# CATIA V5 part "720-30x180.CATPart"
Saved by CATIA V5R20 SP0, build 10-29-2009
Part number: 720-30x180
Definition: NONE
Nomenclature: 720-30x180
Source: Unknown
Description: 720-30x180
Bounding box of the stored display mesh (mm): x 0 to 180, y -15 to 15, z -15 to 15
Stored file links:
  C:\Users\Utente\Desktop\IO LAVORO\3D X SITO CF\X SITO\720\720-30x180.CATPart

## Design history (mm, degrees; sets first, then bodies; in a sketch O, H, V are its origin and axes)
Body1 "720-30x180" (main body)
  Solid1: solid without history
